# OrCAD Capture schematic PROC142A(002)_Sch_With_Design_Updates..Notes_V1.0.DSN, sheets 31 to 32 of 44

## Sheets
31 31. FT4232 UART TO USB BRIDGE: size C; title: FT4232 UART TO USB BRIDGE
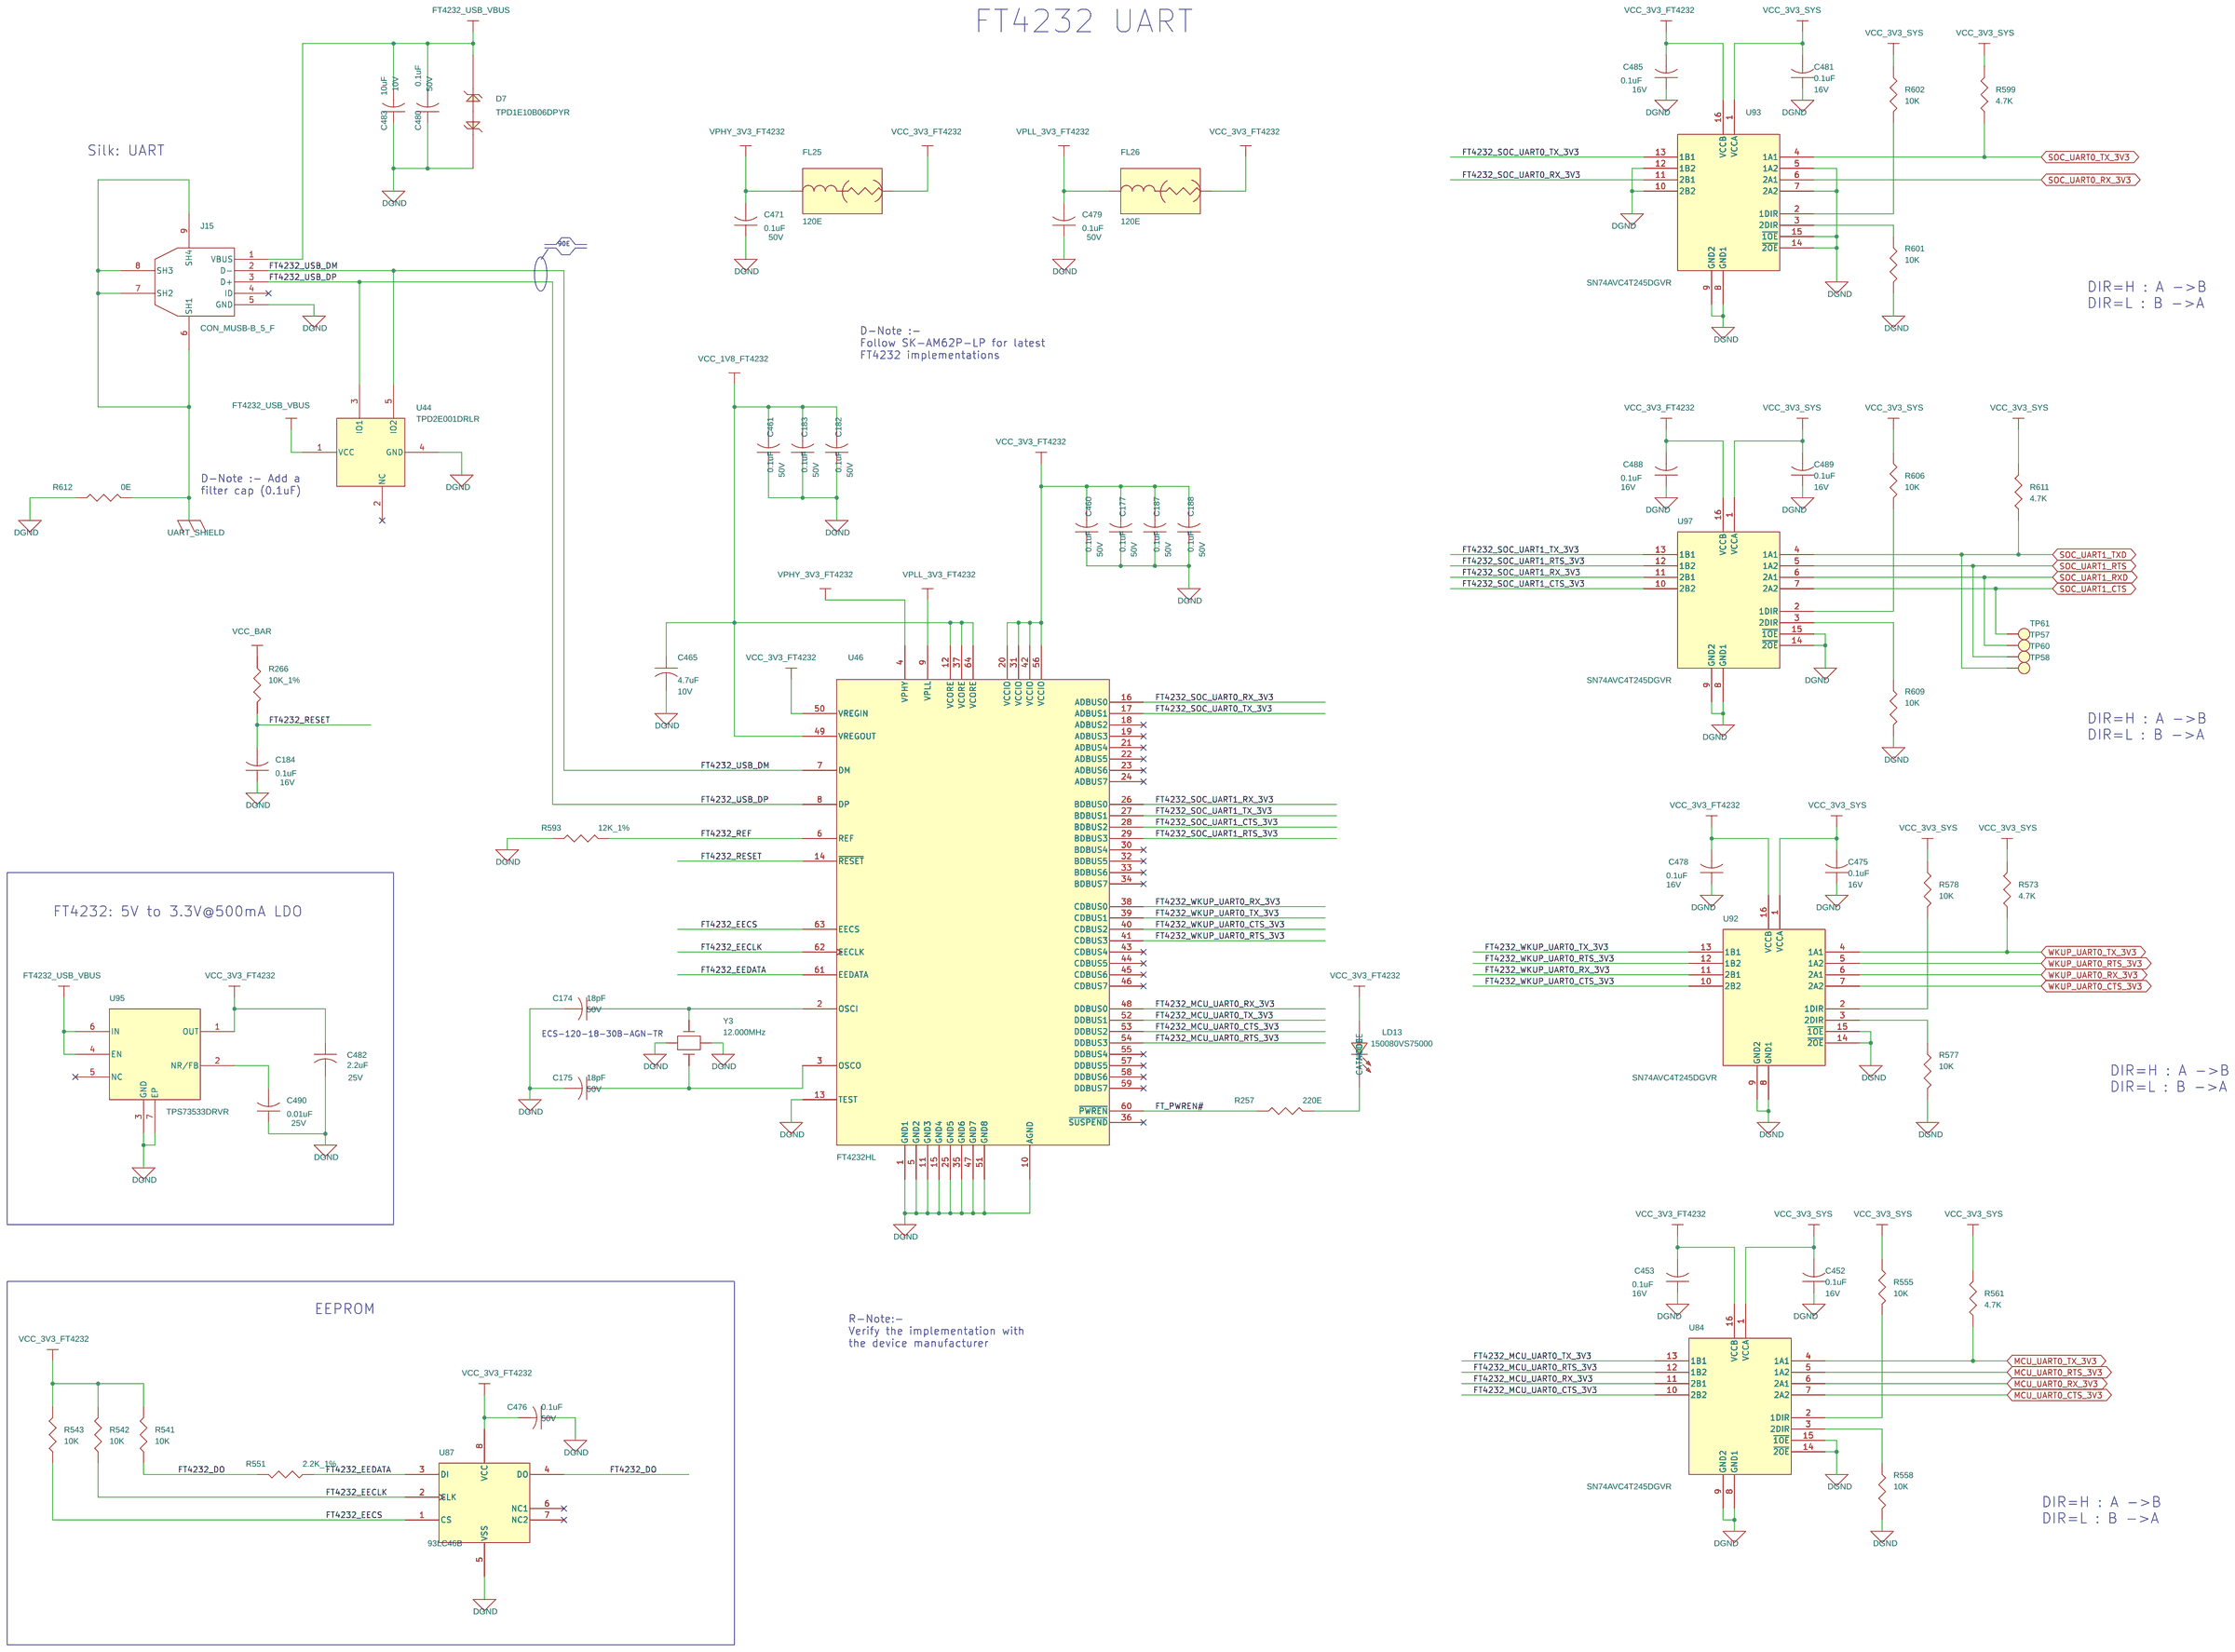
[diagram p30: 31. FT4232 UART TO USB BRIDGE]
32 32. PRU HEADER: size C; title: PRU HEADER
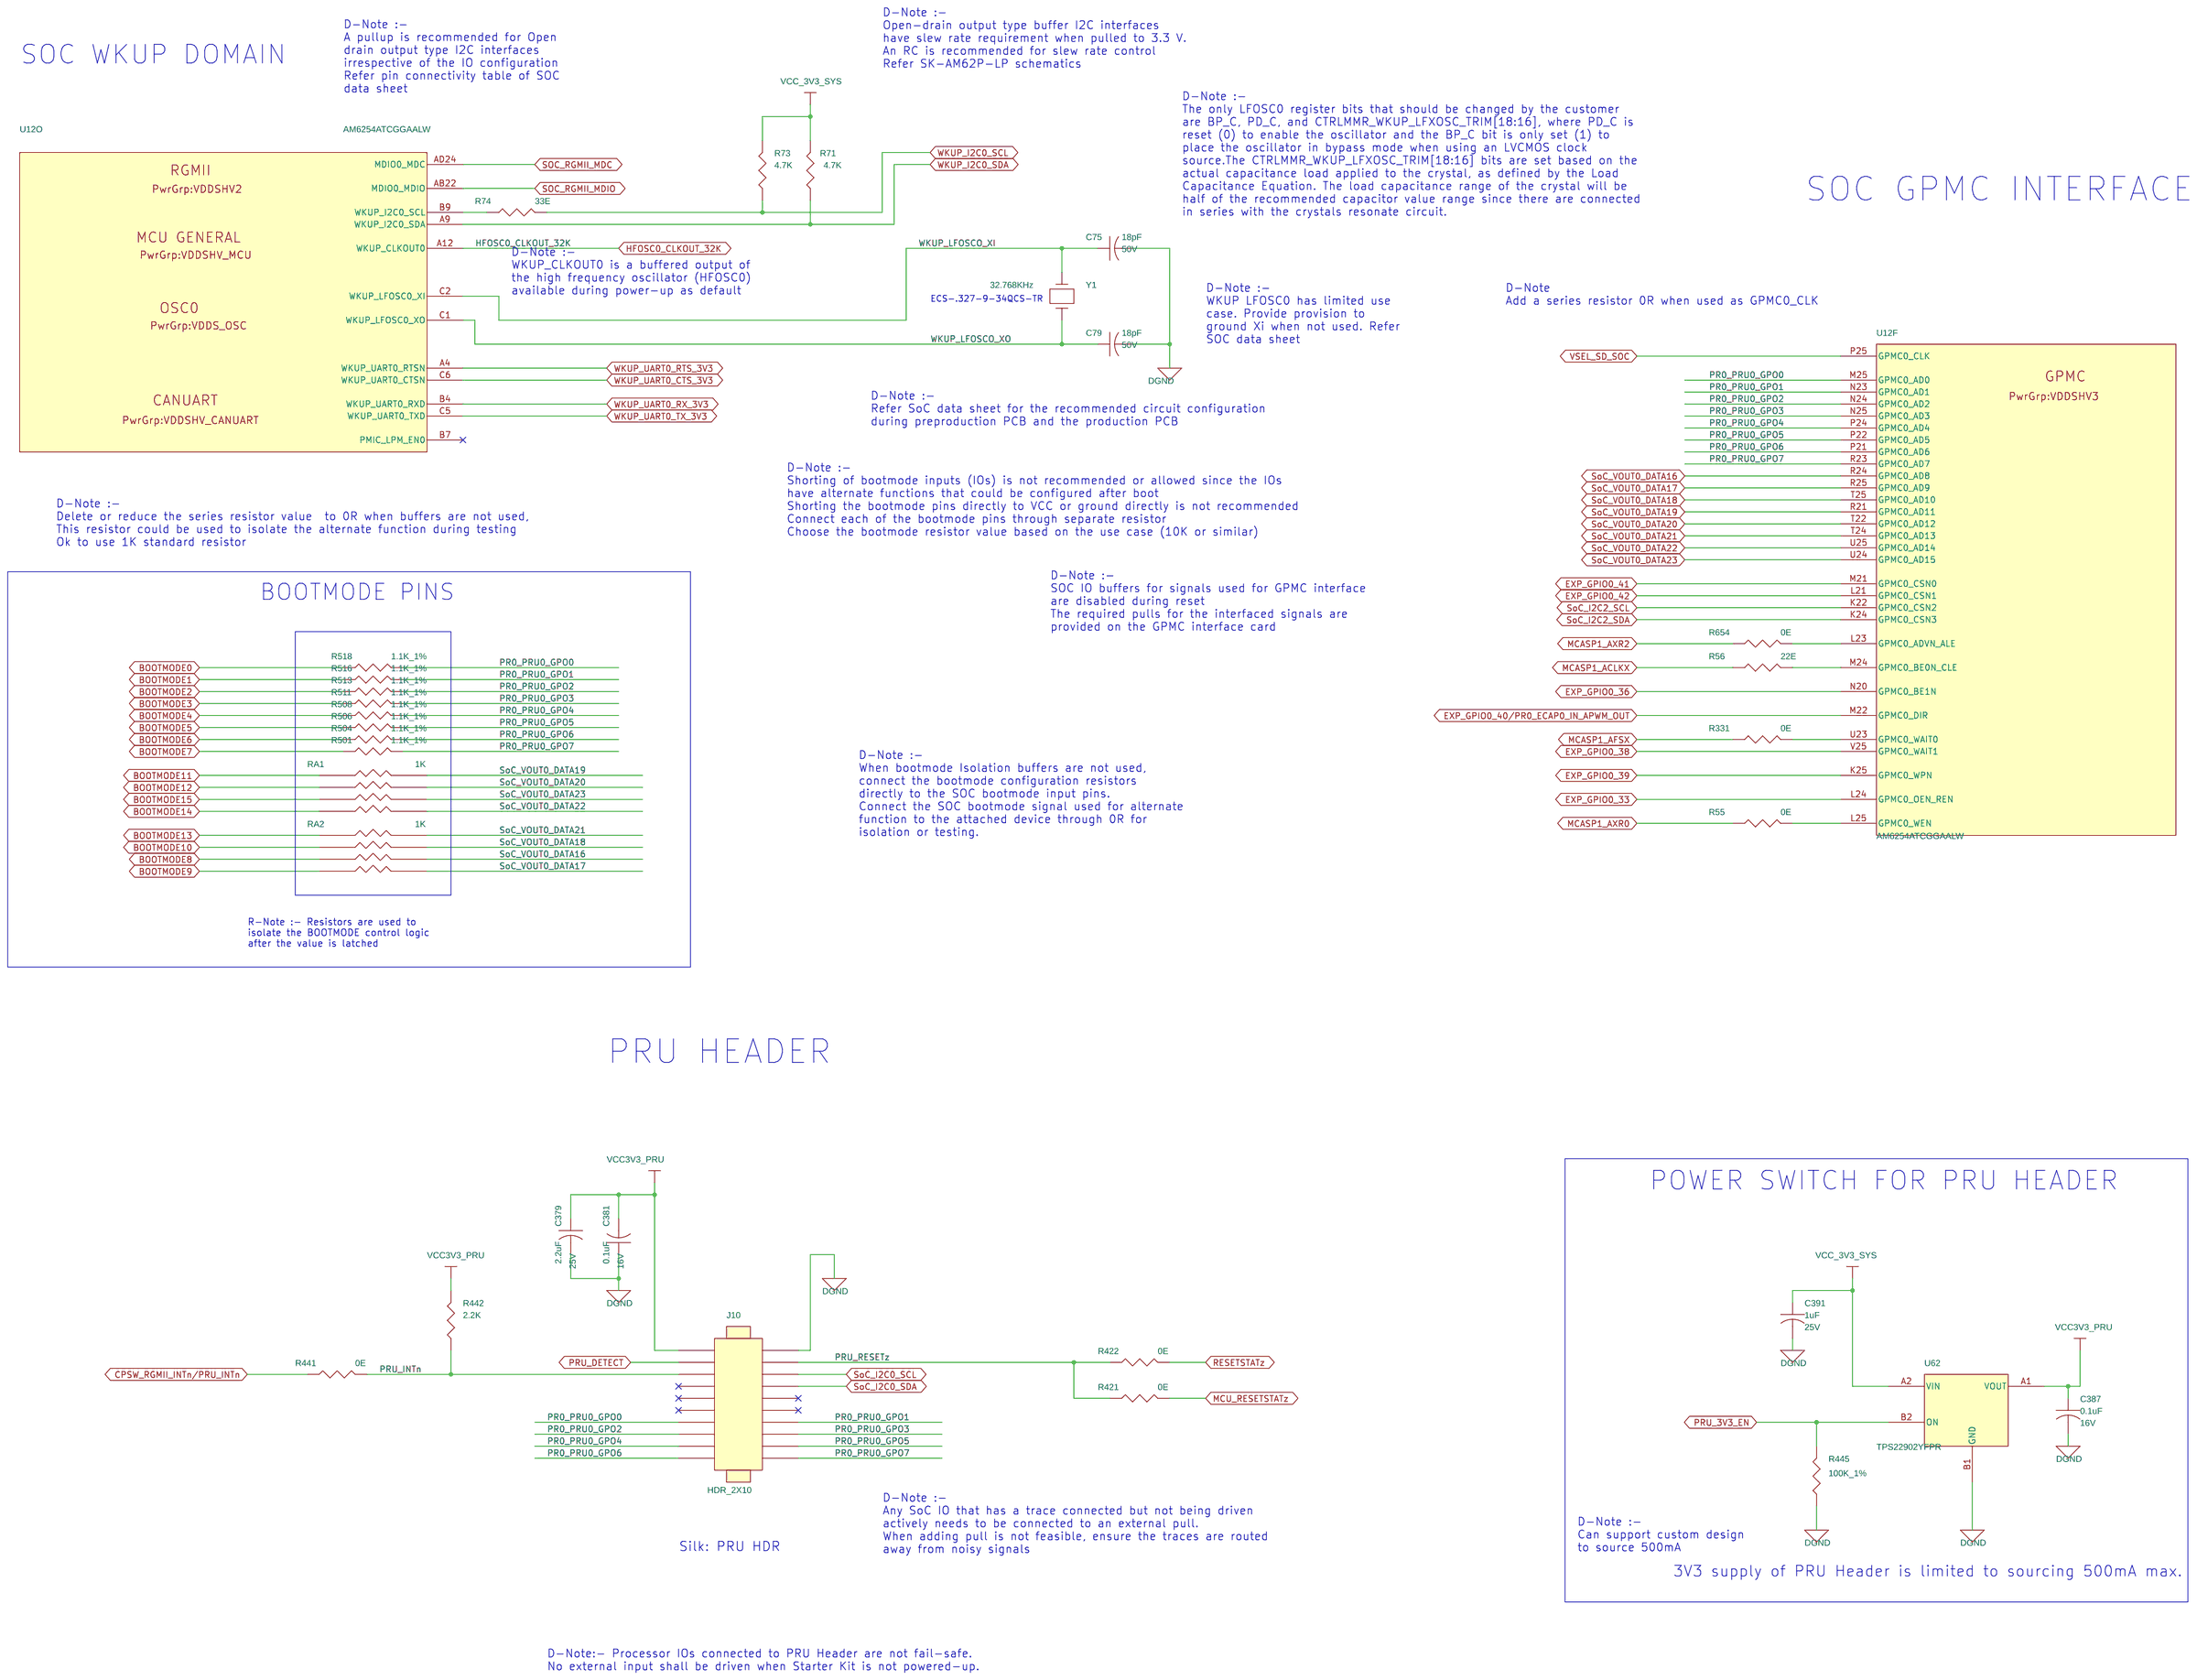
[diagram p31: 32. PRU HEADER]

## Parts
sheet 31. FT4232 UART TO USB BRIDGE
C174  18pF  [CAP0402_0-75]
C175  18pF  [CAP0402_0-75]
C177  0.1uF  [CAP0402_0-75]
C182  0.1uF  [CAP0402_0-75]
C183  0.1uF  [CAP0402_0-75]
C184  0.1uF  [CAP0201_0-5]
C187  0.1uF  [CAP0402_0-75]
C188  0.1uF  [CAP0402_0-75]
C452  0.1uF  [CAP0201_0-5]
C453  0.1uF  [CAP0201_0-5]
C460  0.1uF  [CAP0402_0-75]
C461  0.1uF  [CAP0402_0-75]
C465  4.7uF  [CAP0402_0-75]
C471  0.1uF  [CAP0402_0-75]
C475  0.1uF  [CAP0201_0-5]
C476  0.1uF  [CAP0402_0-75]
C478  0.1uF  [CAP0201_0-5]
C479  0.1uF  [CAP0402_0-75]
C480  0.1uF  [CAP0402_0-75]
C481  0.1uF  [CAP0201_0-5]
C482  2.2uF  [CAP0402_0-75]
C483  10uF  [CAP0402_0-75]
C485  0.1uF  [CAP0201_0-5]
C488  0.1uF  [CAP0201_0-5]
C489  0.1uF  [CAP0201_0-5]
C490  0.01uF  [CAP0201_0-5]
D7  TPD1E10B06DPYR  [DIO_DFN0402_0-5]
FL25  120E  [EMIFIL_BLM15A_0402_0-6]
FL26  120E  [EMIFIL_BLM15A_0402_0-6]
J15  CON_MUSB-B_5_F  [CON_MUSBB5_629105150521_S_R_S_2-7]
LD13  150080VS75000  [LED_150080VS75000_80X50_SMD_0-8]
R257  220E  [RES0402_0-5]
R266  10K_1%  [RES0201_0-5]
R541  10K  [RES0201_0-5]
R542  10K  [RES0201_0-5]
R543  10K  [RES0201_0-5]
R551  2.2K_1%  [RES0201_0-5]
R555  10K  [RES0201_0-5]
R558  10K  [RES0201_0-5]
R561  4.7K  [RES0201_0-5]
R573  4.7K  [RES0201_0-5]
R577  10K  [RES0201_0-5]
R578  10K  [RES0201_0-5]
R593  12K_1%  [RES0402_0-5]
R599  4.7K  [RES0201_0-5]
R601  10K  [RES0201_0-5]
R602  10K  [RES0201_0-5]
R606  10K  [RES0201_0-5]
R609  10K  [RES0201_0-5]
R611  4.7K  [RES0201_0-5]
R612  0E  [RES0805_0-75]
TP57  THRU HOLE  [TP_36X22]
TP58  THRU HOLE  [TP_36X22]
TP60  TP20_SMD  [TP20_SMD]
TP61  TP20_SMD  [TP20_SMD]
U44  TPD2E001DRLR  [SOT553-5_0-6]
U46  FT4232HL  [LQFP64_19-68_390X390_1-6]
U84  SN74AVC4T245DGVR  [TVSOP16_15-74_150X180]
U87  93LC46B  [MSOP8_25-59_125X125_1-1]
U92  SN74AVC4T245DGVR  [TVSOP16_15-74_150X180]
U93  SN74AVC4T245DGVR  [TVSOP16_15-74_150X180]
U95  TPS73533DRVR  [SON6_25-59_85X85]
U97  SN74AVC4T245DGVR  [TVSOP16_15-74_150X180]
Y3  12.000MHz  [XTAL4_ECX-53BQ_200X130_SMD_0-9]
sheet 32. PRU HEADER
C75  18pF  [CAP0402_0-75]
C79  18pF  [CAP0402_0-75]
C379  2.2uF  [CAP0402_0-75]
C381  0.1uF  [CAP0201_0-5]
C387  0.1uF  [CAP0201_0-5]
C391  1uF  [CAP0402_0-75]
J10  HDR_2X10  [HDR_2X10_PREC010DAAN_S_T_8-4]
R55  0E  [RES0201_0-5]
R56  22E  [RES0201_0-5]
R71  4.7K  [RES0201_0-5]
R73  4.7K  [RES0201_0-5]
R74  33E  [RES0201_0-5]
R331  0E  [RES0201_0-5]
R421  0E  [RES0402_0-5]
R422  0E  [RES0201_0-5]
R441  0E  [RES0201_0-5]
R442  2.2K  [RES0201_0-5]
R445  100K_1%  [RES0402_0-5]
R501  1.1K_1%  [RES0201_0-5]
R504  1.1K_1%  [RES0201_0-5]
R506  1.1K_1%  [RES0201_0-5]
R508  1.1K_1%  [RES0201_0-5]
R511  1.1K_1%  [RES0201_0-5]
R513  1.1K_1%  [RES0201_0-5]
R516  1.1K_1%  [RES0201_0-5]
R518  1.1K_1%  [RES0201_0-5]
R654  0E  [RES0201_0-5]
RA1  1K  [RESA_EXB_0201-4_0-5]
RA2  1K  [RESA_EXB_0201-4_0-5]
U62  TPS22902YFPR  [DSBGA4_15-74_30X30_0-5]
Y1  32.768KHz  [XTAL_ECS-32_130X60_SMD_0-9]
sheet 42. OSCILLATOR
U12  AM6254ATCGGAALW  [BGA425_19-68_510X510_0-7]  (sections A,B,C,D,E,F,G,H,I,J,K,L,M,N,O,P,Q,R)

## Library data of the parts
C75 C79 C174 C175 = CAP: CAP CERAMIC 18pF 50V 5% HI-Q C0G(NP0) 0402; Chkd/date: VASANTHA/030315; Crtd /date: NAVEED/271014; Custom_Duty: 15%; Customs_HS_Code: 85322990; Distributor_name: DIGIKEY; Distributor_part_number: 490-3119-1-ND; Footprint Path: Y:\MIS_DATABASE\Library\ALTIUM_TOOL\PCB_FOOTPRINTS\Altium_Footprint_Lib.PcbLib; Height: 0.55MM; Library Path: Y:\MIS_DATABASE\Library\ALTIUM_TOOL\SCHEMATICS_PARTS\MS_DISCRETE_Library.schlib; Mfr_name: MURATA; Mfr_part_number: GJM1555C1H180JB01D; Mistral Part No: 120014100019-R; Package: 0402; Part_type: CAPACITORS\CERAMIC; Project: DC_MIST_RDC; RoHS: RoHS; Temperature: -55°C+125°C; Tolerance: 5%; Voltage: 50V; Wattage: NA; Weight: 6mg; Datasheet: Y:\MIS_DATABASE\DATASHEETS\CAPACITORS\MURATA-GXX-SER_NOV17.PDF
C177 C182 C183 C187 C188 C460 C461 C471 C476 C479 C480 = CAP: CAP CERAMIC 0.1uF 50V 10% X7R 0402; Alt_Mfr_name: YAGEO AMERICA; Alt_Mfr_part_number: CC0402KRX5R8BB104; Chkd/date: MANIRAJA/261020; Crtd /date: ALVY/211020; Custom_Duty: 15%; Customs_HS_Code: 85322990; Distributor_name: DIGIKEY; Distributor_part_number: 490-10700-1-ND; Footprint Path: Y:\MIS_DATABASE\Library\ALTIUM_TOOL\PCB_FOOTPRINTS\Altium_Footprint_Lib.PcbLib; Height: 0.55MM; Library Path: Y:\MIS_DATABASE\Library\ALTIUM_TOOL\SCHEMATICS_PARTS\MS_DISCRETE_Library.schlib; Mfr_name: MURATA; Mfr_part_number: GRM155R71H104KE14D; Mistral Part No: 120011100014-R; Package: 0402; Part_type: CAPACITORS\CERAMIC; Project: J7_CP; RoHS: RoHS; Temperature: -55°C+125°C; Tolerance: 10%; Voltage: 50V; Wattage: NA; Weight: 3.1mg; Datasheet: Y:\MIS_DATABASE\DATASHEETS\CAPACITORS\GRM155R71H104KE14.PDF
C184 C381 C452 C453 C475 C478 C481 C485 C488 C489 = CAP: CAP CERAMIC 0.1uF 16V 10% X5R 0201; Alt_Mfr_name: YAGEO AMERICA; Alt_Mfr_part_number: CC0402KRX5R8BB104; Chkd/date: MANIRAJA/230118; Crtd /date: MANIRAJA/230118; Custom_Duty: 15%; Customs_HS_Code: 85322990; Distributor_name: DIGIKEY; Distributor_part_number: 490-14305-1-ND; Footprint Path: Y:\MIS_DATABASE\Library\ALTIUM_TOOL\PCB_FOOTPRINTS\Altium_Footprint_Lib.PcbLib; Height: 0.33MM; Library Path: Y:\MIS_DATABASE\Library\ALTIUM_TOOL\SCHEMATICS_PARTS\MS_DISCRETE_Library.schlib; Mfr_name: MURATA; Mfr_part_number: GRM033R61C104KE14D; Mistral Part No: 120009030072-R; Package: 0201; Part_type: CAPACITORS\CERAMIC; Project: TI_MAXIE_CPB; RoHS: RoHS; Temperature: -55°C+85°C; Tolerance: 10%; Voltage: 16V; Wattage: NA; Weight: 0.33mg; Datasheet: Y:\MIS_DATABASE\DATASHEETS\CAPACITORS\GRM033R61C104KE14.PDF
C465 = CAP: CAP CERAMIC 4.7uF 10V 20% X5R 0402; Chkd/date: MANIRAJA/110718; Crtd /date: ALVY/110718; Custom_Duty: 15%; Customs_HS_Code: 85322990; Distributor_name: DIGIKEY; Distributor_part_number: 490-14306-1-ND; Footprint Path: Y:\MIS_DATABASE\Library\ALTIUM_TOOL\PCB_FOOTPRINTS\Altium_Footprint_Lib.PcbLib; Height: 0.65MM; Library Path: Y:\MIS_DATABASE\Library\ALTIUM_TOOL\SCHEMATICS_PARTS\MS_DISCRETE_Library.schlib; Mfr_name: MURATA; Mfr_part_number: GRM155R61A475MEAAD; Mistral Part No: 120012060002-R; Package: 0402; Part_type: CAPACITORS\CERAMIC; Project: TI_J7SVB_PCIE_ADD-ON-CARD; RoHS: RoHS; Temperature: -55°C+85°C; Tolerance: 20%; Voltage: 10V; Wattage: NA; Weight: 14mg; Datasheet: Y:\MIS_DATABASE\DATASHEETS\CAPACITORS\GRM155R61A475MEAAD.PDF
C379 C482 = CAP: CAP CERAMIC 2.2uF 25V 10% X5R 0402; Chkd/date: ALVY/010721; Crtd /date: MANIRAJA/010721; Custom_Duty: 15%; Customs_HS_Code: 85322990; Distributor_name: DIGIKEY; Distributor_part_number: 490-12703-1-ND; Footprint Path: Y:\MIS_DATABASE\Library\ALTIUM_TOOL\PCB_FOOTPRINTS\Altium_Footprint_Lib.PcbLib; Height: 0.70MM; Library Path: Y:\MIS_DATABASE\Library\ALTIUM_TOOL\SCHEMATICS_PARTS\MS_DISCRETE_Library.schlib; Mfr_name: MURATA; Mfr_part_number: GRM155R61E225KE11D; Mistral Part No: 120015120001-R; Package: 0402; Part_type: CAPACITORS\CERAMIC; Project: TI_AM263X_CC; RoHS: RoHS; Temperature: -55°C+85°C; Tolerance: 10%; Voltage: 25V; Wattage: NA; Weight: 1.5mg; Datasheet: Y:\MIS_DATABASE\DATASHEETS\CAPACITORS\GRM155R61E225KE11.PDF
C483 = CAP: CAP CERAMIC 10uF 10V 20% X5R 0402; Chkd/date: MANIRAJA/300520; Crtd /date: ALVY/260520; Custom_Duty: 15%; Customs_HS_Code: 85322990; Distributor_name: DIGIKEY; Distributor_part_number: 490-GRM155R61A106ME11DTR-ND; Footprint Path: Y:\MIS_DATABASE\Library\ALTIUM_TOOL\PCB_FOOTPRINTS\Altium_Footprint_Lib.PcbLib; Height: 0.55MM; Library Path: Y:\MIS_DATABASE\Library\ALTIUM_TOOL\SCHEMATICS_PARTS\MS_DISCRETE_Library.schlib; Mfr_name: MURATA; Mfr_part_number: GRM155R61A106ME11D; Mistral Part No: 120013110019-R; Package: 0402; Part_type: CAPACITORS\CERAMIC; Project: QCS610_NANOSOM; RoHS: RoHS; Temperature: -55°C+85°C; Tolerance: 20%; Voltage: 10V; Wattage: NA; Weight: 3.1mg; Datasheet: Y:\MIS_DATABASE\DATASHEETS\CAPACITORS\MURATA-GXX-SER_NOV17.PDF
C490 = CAP: CAP CERAMIC 0.01uF 25V 10% X5R 0201; Chkd/date: MANIRAJA/230118; Crtd /date: MANIRAJA/230118; Custom_Duty: 15%; Customs_HS_Code: 85322990; Distributor_name: DIGIKEY; Distributor_part_number: GRM033R61E103KA12J-ND; Footprint Path: Y:\MIS_DATABASE\Library\ALTIUM_TOOL\PCB_FOOTPRINTS\Altium_Footprint_Lib.PcbLib; Height: 0.33MM; Library Path: Y:\MIS_DATABASE\Library\ALTIUM_TOOL\SCHEMATICS_PARTS\MS_DISCRETE_Library.schlib; Mfr_name: MURATA; Mfr_part_number: GRM033R61E103KA12J; Mistral Part No: 120018010007-R; Package: 0201; Part_type: CAPACITORS\CERAMIC; Project: TI_MAXIE_CPB; RoHS: RoHS; Temperature: -55°C+85°C; Tolerance: 10%; Voltage: 25V; Wattage: NA; Weight: 0.33mg; Datasheet: Y:\MIS_DATABASE\DATASHEETS\CAPACITORS\GRM033R61E103KA12.PDF
D7 = DIODE_SOD323: DIODE 1CH ESD PROTECTION X1SON2; Chkd/date: MANIRAJA/040420; Crtd /date: VASANTHA/181114; Custom_Duty: 15%; Customs_HS_Code: 85423100; Distributor_name: DIGIKEY; Distributor_part_number: 296-30406-1-ND; Footprint Path: Y:\MIS_DATABASE\Library\ALTIUM_TOOL\PCB_FOOTPRINTS\Altium_Footprint_Lib.PcbLib; Height: 0.45MM; Library Path: Y:\MIS_DATABASE\Library\ALTIUM_TOOL\SCHEMATICS_PARTS\MS_DISCRETE_Library.schlib; Mfr_name: TEXAS INSTRUMENTS; Mistral Part No: 130014110022-R; Package: X1SON2; Part_type: DIODE; Project: GALILEO_EVM; RoHS: RoHS; Temperature: -40°C+125°C; Tolerance: NA; Voltage: NA; Wattage: NA; Weight: 1mg; Datasheet: Y:\MIS_DATABASE\DATASHEETS\ICS\INTERFACE\TPD1E10B06-SER.PDF
FL25 FL26 = EMIFILTER_IND: IND FERRITE BEAD CHIP 120E 2A 0402; Chkd/date: NAVEED/241114; Crtd /date: USMAN/170613; Custom_Duty: 24%; Customs_HS_Code: 85369090; Distributor_name: DIGIKEY; Distributor_part_number: 490-9656-1-ND; Footprint Path: Y:\MIS_DATABASE\Library\ALTIUM_TOOL\PCB_FOOTPRINTS\Altium_Footprint_Lib.PcbLib; Height: 0.55MM; Library Path: Y:\MIS_DATABASE\Library\ALTIUM_TOOL\SCHEMATICS_PARTS\MS_FILTER_Library.schlib; Mfr_name: MURATA; Mfr_part_number: BLM15PX121SN1D; Mistral Part No: 130013060022-R; Package: 0402; Part_type: INDUCTOR; Project: GEN_3-8; RoHS: RoHS; Temperature: -55°C+125°C; Tolerance: 25%; Voltage: NA; Wattage: NA; Weight: 1mg; Datasheet: Y:\MIS_DATABASE\DATASHEETS\DISCRETES\INDUCTORS\BLM15-SN1-SER.PDF
J15 = CON_USB_MINI-B: CON MICRO USB TYPE B 5POS FEMALE RT SMD; Chkd/date: MANIRAJA/150519; Crtd /date: ALVY/150519; Custom_Duty: 24%; Customs_HS_Code: 85369090; Distributor_name: DIGIKEY; Distributor_part_number: 732-5960-1-ND; Footprint Path: Y:\MIS_DATABASE\Library\ALTIUM_TOOL\PCB_FOOTPRINTS\Altium_Footprint_Lib.PcbLib; Height: 2.66MM; Library Path: Y:\MIS_DATABASE\Library\ALTIUM_TOOL\SCHEMATICS_PARTS\MS_CONNECTOR_Library.schlib; Mfr_name: WURTH ELECTRONICS; Mfr_part_number: 629105150521; Mistral Part No: 150019050015-R; Package: SMD; Part_type: CONNECTOR\USB; Project: NEXTNAV_ALT-STATION_ATE_BRD; RoHS: RoHS; Temperature: -40°C+85°C; Tolerance: NA; Voltage: NA; Wattage: NA; Weight: 360mg; Datasheet: Y:\MIS_DATABASE\DATASHEETS\CONNECTORS\629105150521.PDF
LD13 = DIODE_LED: DIODE LED BRIGHT GREEN SMD; Chkd/date: MANIRAJA/180820; Crtd /date: ALVY/180820; Custom_Duty: 24%; Customs_HS_Code: 85439000; Distributor_name: DIGIKEY; Distributor_part_number: 732-4986-1-ND; Footprint Path: Y:\MIS_DATABASE\Library\ALTIUM_TOOL\PCB_FOOTPRINTS\Altium_Footprint_Lib.PcbLib; Height: 0.80MM; Library Path: Y:\MIS_DATABASE\Library\ALTIUM_TOOL\SCHEMATICS_PARTS\MS_OPTO_Library.schlib; Mfr_name: WURTH ELECTRONICS; Mistral Part No: 130020080012-R; Package: SMD; Part_type: OPTO\LED; Project: AM64x_EVM_BRD; RoHS: RoHS; Temperature: -40°C+85°C; Tolerance: NA; Voltage: NA; Wattage: NA; Weight: 10mg; Datasheet: Y:\MIS_DATABASE\DATASHEETS\DISCRETES\LEDS\150080VS75000.PDF
R257 = RESISTOR: RES 220E 1/10W 5% 0402; Chkd/date: VASANTHA/291216; Crtd /date: GEETHA/260406; Custom_Duty: 15%; Customs_HS_Code: 85332119; Distributor_name: DIGIKEY; Distributor_part_number: P220JCT-ND; Footprint Path: Y:\MIS_DATABASE\Library\ALTIUM_TOOL\PCB_FOOTPRINTS\Altium_Footprint_Lib.PcbLib; Height: 0.40MM; Library Path: Y:\MIS_DATABASE\Library\ALTIUM_TOOL\SCHEMATICS_PARTS\MS_DISCRETE_Library.schlib; Mfr_name: PANASONIC-ECG; Mfr_part_number: ERJ-2GEJ221X; Mistral Part No: 110009030506-R; Package: 0402; Part_type: RESISTORS\FIXED; Project: RED EYE; RoHS: RoHS; Temperature: -55°C+155°C; Tolerance: 5%; Voltage: NA; Wattage: 1/10W; Weight: 0.8mg; Datasheet: Y:\MIS_DATABASE\DATASHEETS\RESISTORS\PAN-ERJSER_NOV17.PDF
R266 = RESISTOR: RES 10K 1/20W 1% 0201; Chkd/date: VASANTHA/270117; Crtd /date: MANIRAJA/270117; Custom_Duty: 15%; Customs_HS_Code: 85332119; Distributor_name: DIGIKEY; Distributor_part_number: 311-10.0KMCT-ND; Footprint Path: Y:\MIS_DATABASE\Library\ALTIUM_TOOL\PCB_FOOTPRINTS\Altium_Footprint_Lib.PcbLib; Height: 0.26MM; Library Path: Y:\MIS_DATABASE\Library\ALTIUM_TOOL\SCHEMATICS_PARTS\MS_DISCRETE_Library.schlib; Mfr_name: YAGEO AMERICA; Mfr_part_number: RC0201FR-0710KL; Mistral Part No: 110011040018-R; Package: 0201; Part_type: RESISTORS\FIXED; Project: GOLDEN-I LITE; RoHS: RoHS; Temperature: -55°C+125°C; Tolerance: 1%; Voltage: NA; Wattage: 1/20W; Weight: 0.17mg; Datasheet: Y:\MIS_DATABASE\DATASHEETS\RESISTORS\RCXXXXL-SER_MAR18.PDF
R541-R543 R555 R558 R577 R578 R601 R602 R606 R609 = RESISTOR: RES 10K 1/20W 5% 0201; Chkd/date: MANIRAJA/050517; Crtd /date: MANIRAJA/050517; Custom_Duty: 15%; Customs_HS_Code: 85332119; Distributor_name: DIGIKEY; Distributor_part_number: 311-10KNCT-ND; Footprint Path: Y:\MIS_DATABASE\Library\ALTIUM_TOOL\PCB_FOOTPRINTS\Altium_Footprint_Lib.PcbLib; Height: 0.26MM; Library Path: Y:\MIS_DATABASE\Library\ALTIUM_TOOL\SCHEMATICS_PARTS\MS_DISCRETE_Library.schlib; Mfr_name: YAGEO AMERICA; Mfr_part_number: RC0201JR-0710KL; Mistral Part No: 110010070051-R; Package: 0201; Part_type: RESISTORS\FIXED; Project: GOLDEN-I LITE; RoHS: RoHS; Temperature: -55°C+125°C; Tolerance: 5%; Voltage: NA; Wattage: 1/20W; Weight: 0.17mg; Datasheet: Y:\MIS_DATABASE\DATASHEETS\RESISTORS\RCXXXXL-SER_MAR18.PDF
R551 = RESISTOR: RES 2.2K 1/20W 1% 0201; Chkd/date: VASANTHA/270117; Crtd /date: MANIRAJA/270117; Custom_Duty: 15%; Customs_HS_Code: 85332119; Distributor_name: DIGIKEY; Distributor_part_number: YAG2572CT-ND; Footprint Path: Y:\MIS_DATABASE\Library\ALTIUM_TOOL\PCB_FOOTPRINTS\Altium_Footprint_Lib.PcbLib; Height: 0.26MM; Library Path: Y:\MIS_DATABASE\Library\ALTIUM_TOOL\SCHEMATICS_PARTS\MS_DISCRETE_Library.schlib; Manufacturer: YAGEO AMERICA; Mfr_name: PANASONIC-ECG; Mfr_part_number: RC0201FR-072K2L; Mistral Part No: 110017010016-R; Package: 0201; Part_type: RESISTORS\FIXED; Project: GOLDEN-I LITE; RoHS: RoHS; Temperature: -55°C+125°C; Tolerance: 1%; Voltage: NA; Wattage: 1/20W; Weight: 0.17mg; Datasheet: Y:\MIS_DATABASE\DATASHEETS\RESISTORS\RCXXXXL-SER_MAR18.PDF
R71 R73 R561 R573 R599 R611 = RESISTOR: RES 4.7K 1/20W 5% 0201; Chkd/date: MANIRAJA/200921; Crtd /date: ALVY/200921; Custom_Duty: 15%; Customs_HS_Code: 85332119; Distributor_name: DIGIKEY; Distributor_part_number: 311-4.7KNCT-ND; Footprint Path: Y:\MIS_DATABASE\Library\ALTIUM_TOOL\PCB_FOOTPRINTS\Altium_Footprint_Lib.PcbLib; Height: 0.26MM; Library Path: Y:\MIS_DATABASE\Library\ALTIUM_TOOL\SCHEMATICS_PARTS\MS_DISCRETE_Library.schlib; Mfr_name: YAGEO AMERICA; Mfr_part_number: RC0201JR-074K7L; Mistral Part No: 110021090007-R; Package: 0201; Part_type: RESISTORS\FIXED; Project: TI_AM62x SKEVM_BRD; RoHS: RoHS; Temperature: -55°C+125°C; Tolerance: 5%; Voltage: NA; Wattage: 1/20W; Weight: 0.17mg; Datasheet: Y:\MIS_DATABASE\DATASHEETS\RESISTORS\RCXXXXL-SER_MAR18.PDF
R593 = RESISTOR: RES 12K 1/10W 1% 0402; Chkd/date: VASANTHA/041215; Crtd /date: VASANTHA/041215; Custom_Duty: 15%; Customs_HS_Code: 85332119; Distributor_name: DIGIKEY; Distributor_part_number: P12.0KLCT-ND; Footprint Path: Y:\MIS_DATABASE\Library\ALTIUM_TOOL\PCB_FOOTPRINTS\Altium_Footprint_Lib.PcbLib; Height: 0.40MM; Library Path: Y:\MIS_DATABASE\Library\ALTIUM_TOOL\SCHEMATICS_PARTS\MS_DISCRETE_Library.schlib; Mfr_name: PANASONIC-ECG; Mfr_part_number: ERJ-2RKF1202X; Mistral Part No: 110019040053-R; Package: 0402; Part_type: RESISTORS\FIXED; Project: TI_C5545; RoHS: RoHS; Temperature: -55°C+155°C; Tolerance: 1%; Voltage: NA; Wattage: 1/10W; Weight: 0.8mg; Datasheet: Y:\MIS_DATABASE\DATASHEETS\RESISTORS\PAN-ERJSER_NOV17.PDF
R612 = RESISTOR: RES 0E 1/8W 5% 0805; Chkd/date: VASANTHA/130416; Crtd /date: JEBRAN/020316; Custom_Duty: 15%; Customs_HS_Code: 85332119; Distributor_name: DIGIKEY; Distributor_part_number: 311-0.0ARCT-ND; Footprint Path: Y:\MIS_DATABASE\Library\ALTIUM_TOOL\PCB_FOOTPRINTS\Altium_Footprint_Lib.PcbLib; Height: 0.60MM; Library Path: Y:\MIS_DATABASE\Library\ALTIUM_TOOL\SCHEMATICS_PARTS\MS_DISCRETE_Library.schlib; Mfr_name: YAGEO AMERICA; Mfr_part_number: RC0805JR-070RL; Mistral Part No: 110009030074-R; Package: 0805; Part_type: RESISTORS\FIXED; Project: ZK_BIOMETRIC; RoHS: RoHS; Temperature: -55°C+155°C; Tolerance: 5%; Voltage: NA; Wattage: 1/8W; Weight: 5.5mg; Datasheet: Y:\MIS_DATABASE\DATASHEETS\RESISTORS\RCXXXXL-SER_MAR18.PDF
TP57 TP58 = TESTPOINT: TESTPOINT 0.56MM DRILL PTH; Chkd/date: BAVISH/040311; Crtd /date: MAZHAR/110405; Distributor_name: NA; Distributor_part_number: NA; Height: NA; Mfr_name: LOCAL; Mistral Part No: 130010010008; Package: THRU-HOLE; Project: KOPIN_MODULS; Temperature: NA; Tolerance: NA; Voltage: NA; Wattage: NA; Weight: NA; Datasheet: NA
TP60 TP61 = TESTPOINT: TESTPOINT CIR 20 SMD; Chkd/date: SHREESHAIL/171006; Crtd /date: MAZHAR/171006; Custom_Duty: NA; Customs_HS_Code: NA; Distributor_name: NA; Distributor_part_number: NA; Footprint Path: Y:\MIS_DATABASE\Library\ALTIUM_TOOL\PCB_FOOTPRINTS\Altium_Footprint_Lib.PcbLib; Height: NA; Library Path: Y:\MIS_DATABASE\Library\ALTIUM_TOOL\SCHEMATICS_PARTS\MS_DISCRETE_Library.schlib; MECHANICAL 3D STEP FILE: NA; Mfr_name: LOCAL; Mistral Part No: NA; Package: SMD; Project: BT MODULE_CSRBC04; RoHS: NA; Temperature: NA; Tolerance: NA; Voltage: NA; Wattage: NA; Weight: NA; Datasheet: NA
U44 = TPD2E001DRLR_SOT-5: IC ESD-PROTECTION DIODE ARRAYS SOT-5; Chkd/date: NAVEED/150714; Crtd /date: MUDDU/250510; Custom_Duty: 15%; Customs_HS_Code: 85423100; Distributor_name: DIGIKEY; Distributor_part_number: 296-21883-1-ND; Footprint Path: Y:\MIS_DATABASE\Library\ALTIUM_TOOL\PCB_FOOTPRINTS\Altium_Footprint_Lib.PcbLib; Height: 0.60MM; Library Path: Y:\MIS_DATABASE\Library\ALTIUM_TOOL\SCHEMATICS_PARTS\MS_FILTER_Library.schlib; Mfr_name: TEXAS INSTRUMENTS; Mistral Part No: 140110060007-R; Package: SOT-5; Part_type: ICS\ANALOG\ACTIVE FILTER; Project: CENTAURUS; RoHS: RoHS; Temperature: -40°C+85°C; Tolerance: NA; Voltage: NA; Wattage: NA; Weight: 2.8mg; Datasheet: Y:\MIS_DATABASE\DATASHEETS\ICS\MISC\TPD2E001DRLR.PDF
U46 = FT4232H_LQFP64: IC HIGH SPEED QUAD USB UART LQFP64; Chkd/date: MANIRAJA/110917; Crtd /date: VIJAYALAKSHMI/120813; Custom_Duty: 15%; Customs_HS_Code: 85423100; Distributor_name: DIGIKEY; Distributor_part_number: 768-1026-1-ND; Footprint Path: Y:\MIS_DATABASE\Library\ALTIUM_TOOL\PCB_FOOTPRINTS\Altium_Footprint_Lib.PcbLib; Height: 1.60MM; Library Path: Y:\MIS_DATABASE\Library\ALTIUM_TOOL\SCHEMATICS_PARTS\MS_COMBINATIONAL_Library.schlib; Mfr_name: FTDI; Mfr_part_number: FT4232HL-REEL; Mistral Part No: 141013080006-R; Package: LQFP64; Part_type: ICS\DIGITAL\PERIPHERAL; Project: DM37XX; RoHS: RoHS; Temperature: -40°C+85°C; Tolerance: NA; Voltage: NA; Wattage: NA; Weight: 342.7mg; Datasheet: Y:\MIS_DATABASE\DATASHEETS\ICS\DIGITAL\PERIPHERAL\FT4232HX.PDF
U84 U92 U93 U97 = SN74AVC4T245DGVR_TVSOP16: IC 4-BIT DUAL SUPPLY BUS TRANSCEIVER TVSOP16; Chkd/date: SUHAS/251010; Crtd /date: MAZHAR/201109; Custom_Duty: 15%; Customs_HS_Code: 85423100; Distributor_name: DIGIKEY; Distributor_part_number: 296-18054-1-ND; Height: 1.20MM; Mfr_name: TEXAS INSTRUMENTS; Mistral Part No: 141009110005-P; Package: TVSOP16; Part_type: ICS\DIGITAL\COMBINATIONAL; Project: GOLDEN-I; RoHS: Sb/ Br FREE; Temperature: -40°C+85°C; Datasheet: Y:\MIS_DATABASE\DATASHEETS\ICS\DIGITAL\BUSTRANSCEIVER\SN74AVC4T245.PDF
U87 = 93LC46B_MSOP8: IC 1K MICROWIRE COMPATIBLE SERIAL EEPROM MSOP8; Chkd/date: MANIRAJA/150218; Crtd /date: ALVY/150218; Custom_Duty: 15%; Customs_HS_Code: 85423100; Distributor_name: DIGIKEY; Distributor_part_number: 93LC46B-I/MS-ND; Footprint Path: Y:\MIS_DATABASE\Library\ALTIUM_TOOL\PCB_FOOTPRINTS\Altium_Footprint_Lib.PcbLib; Height: 1.10MM; Library Path: Y:\MIS_DATABASE\Library\ALTIUM_TOOL\SCHEMATICS_PARTS\MS_MISCMEMORY_Library.schlib; Mfr_name: MICROCHIP; Mfr_part_number: 93LC46B-I/MS; Mistral Part No: 141118020002-R; Package: MSOP8; Part_type: ICS\DIGITAL\MEMORY; Project: TI_MAXIE_CPB; RoHS: RoHS; Temperature: -40°C+85°C; Tolerance: NA; Voltage: NA; Wattage: NA; Weight: 140mg; Datasheet: Y:\MIS_DATABASE\DATASHEETS\ICS\MEMORY\93LC46B.PDF
U95 = TPS73501DRVR_SON6: IC 500mA LOW DROPOUT REGULATOR SON6; Chkd/date: VASANTHA/280915; Crtd /date: NAVEED/011014; Custom_Duty: 15%; Customs_HS_Code: 85423100; Distributor_name: DIGIKEY; Distributor_part_number: TPS73533DRVR-ND; Height: 0.80MM; Mfr_name: TEXAS INSTRUMENTS; Mistral Part No: 142014100001-R; Package: SON6; Part_type: ICS\POWER\VOLTAGE REGULATOR; Project: BLUETOOTH_WATCH; RoHS: RoHS; Temperature: -40°C+125°C; Tolerance: NA; Voltage: NA; Wattage: NA; Weight: NA; Datasheet: Y:\MIS_DATABASE\DATASHEETS\ICS\POWER\TPS735.PDF
Y3 = CRY4_13: CRY 12.000MHz 18pF SMD; Chkd/date: MANIRAJA/271021; Crtd /date: ALVY/271021; Custom_Duty: 24%; Customs_HS_Code: 85439000; Distributor_name: DIGIKEY; Distributor_part_number: XC2719CT-ND; Footprint Path: Y:\MIS_DATABASE\Library\ALTIUM_TOOL\PCB_FOOTPRINTS\Altium_Footprint_Lib.PcbLib; Height: 0.85MM; Library Path: Y:\MIS_DATABASE\Library\ALTIUM_TOOL\SCHEMATICS_PARTS\MS_DISCRETE_Library.schlib; Mfr_name: ECS INC; Mfr_part_number: ECS-120-18-30B-AGN-TR; Mistral Part No: 130021100037-R; Package: SMD; Part_type: CRYSTAL; Project: TI_AM62x SKEVM_BRD; RoHS: RoHS; Temperature: -40°C+85°C; Tolerance: NA; Voltage: NA; Wattage: NA; Weight: 159.425mg; Datasheet: Y:\MIS_DATABASE\DATASHEETS\MISC\CRY_OSC\ECS-53B.PDF
C387 = CAP: CAP CERAMIC 0.1uF 16V 10% X5R 0201; Chkd/date: PRADEEP/130623; Crtd /date: PRADEEP/130623; Custom_Duty: 15%; Customs_HS_Code: 85322990; Distributor_name: NA; Distributor_part_number: NA; Footprint Path: Y:\MIS_DATABASE\Library\ALTIUM_TOOL\PCB_FOOTPRINTS\Altium_Footprint_Lib.PcbLib; Height: 0.33MM; Library Path: Y:\MIS_DATABASE\Library\ALTIUM_TOOL\SCHEMATICS_PARTS\MS_DISCRETE_Library.schlib; Mfr_name: MURATA; Mfr_part_number: GRT033R61C104KE01; Mistral Part No: 120022060019-R; Package: 0201; Part_type: CAPACITORS\CERAMIC; Project: AM62P_SK; RoHS: RoHS; Temperature: -55°C+85°C; Tolerance: 10%; Voltage: 16V; Wattage: NA; Weight: 0.33mg; Datasheet: Y:\MIS_DATABASE\DATASHEETS\CAPACITORS\GRT033R61C104KE01XX.PDF
C391 = CAP: CAP CERAMIC 1uF 25V 10% X6S 0402; Chkd/date: MANIRAJA/140518; Crtd /date: ALVY/140518; Custom_Duty: 15%; Customs_HS_Code: 85322990; Distributor_name: DIGIKEY; Distributor_part_number: 490-10014-1-ND; Footprint Path: Y:\MIS_DATABASE\Library\ALTIUM_TOOL\PCB_FOOTPRINTS\Altium_Footprint_Lib.PcbLib; Height: 0.60MM; Library Path: Y:\MIS_DATABASE\Library\ALTIUM_TOOL\SCHEMATICS_PARTS\MS_DISCRETE_Library.schlib; Mfr_name: MURATA; Mfr_part_number: GRM155C81E105KE11D; Mistral Part No: 120018050004-R; Package: 0402; Part_type: CAPACITORS\CERAMIC; Project: TI_SVB_MAXWELL_DUT; RoHS: RoHS; Temperature: -55°C+105°C; Tolerance: 10%; Voltage: 25V; Wattage: NA; Weight: 6mg; Datasheet: Y:\MIS_DATABASE\DATASHEETS\CAPACITORS\GRM155C81E105KE11X.PDF
J10 = HEADER_10X2: CON HDR 2X10 2.54MM PITCH ST TH; Chkd/date: MANIRAJA/270721; Crtd /date: ALVY/260721; Custom_Duty: 24%; Customs_HS_Code: 85369090; Distributor_name: DIGIKEY; Distributor_part_number: S2012EC-10-ND; Footprint Path: Y:\MIS_DATABASE\Library\ALTIUM_TOOL\PCB_FOOTPRINTS\Altium_Footprint_Lib.PcbLib; Height: 8.34MM; Library Path: Y:\MIS_DATABASE\Library\ALTIUM_TOOL\SCHEMATICS_PARTS\MS_CONNECTOR_Library.schlib; Mfr_name: SULLINS CONNECTOR; Mfr_part_number: PREC010DAAN-RC; Mistral Part No: 150021070022-R; Package: THRU-HOLE; Part_type: CONNECTOR\HEADERS; Project: TI_AM335x SK_BRD; RoHS: RoHS; Temperature: -40°C+105°C; Tolerance: NA; Voltage: NA; Wattage: NA; Weight: NA; Datasheet: Y:\MIS_DATABASE\DATASHEETS\CONNECTORS\PRPCXXDXXN-SER.PDF
R55 R331 R654 = RESISTOR: RES 0E 1/20W 5% 0201; Chkd/date: NAVEED/301214; Crtd /date: MUDDU/120710; Custom_Duty: 15%; Customs_HS_Code: 85332119; Distributor_name: DIGIKEY; Distributor_part_number: 311-0.0NCT-ND; Footprint Path: Y:\MIS_DATABASE\Library\ALTIUM_TOOL\PCB_FOOTPRINTS\Altium_Footprint_Lib.PcbLib; Height: 0.26MM; Library Path: Y:\MIS_DATABASE\Library\ALTIUM_TOOL\SCHEMATICS_PARTS\MS_DISCRETE_Library.schlib; Mfr_name: YAGEO AMERICA; Mfr_part_number: RC0201JR-070RL; Mistral Part No: 110010070067-R; Package: 0201; Part_type: RESISTORS\FIXED; Project: PB_BUGBASE; RoHS: RoHS; SIGNAL_MODEL: RESISTOR_RES0201_0-5_0E_0E; Temperature: -55°C+125°C; Tolerance: 5%; Voltage: NA; Wattage: 1/20W; Weight: 0.17mg; Datasheet: Y:\MIS_DATABASE\DATASHEETS\RESISTORS\RCXXXXL-SER_MAR18.PDF
R56 = RESISTOR: RES 22E 1/20W 5% 0201; Chkd/date: PRADEEP/220424; Crtd /date: SHANKARI/220424; Custom_Duty: 15%; Customs_HS_Code: 85332119; Distributor_name: DIGIKEY; Distributor_part_number: 311-22NCT-ND; Footprint Path: Y:\MIS_DATABASE\Library\ALTIUM_TOOL\PCB_FOOTPRINTS\Altium_Footprint_Lib.PcbLib; Height: 0.26MM; Library Path: Y:\MIS_DATABASE\Library\ALTIUM_TOOL\SCHEMATICS_PARTS\MS_DISCRETE_Library.schlib; Manufacturer: YAGEO; Mfr_name: YAGEO AMERICA; Mfr_part_number: RC0201JR-0722RL; Mistral Part No: 110024040012-R; Package: 0201; Part_type: RESISTORS\FIXED; Project: J7AEN_SKEVM; RoHS: RoHS; Temperature: -55°C+125°C; Tolerance: 5%; Voltage: NA; Wattage: 1/20W; Weight: NA; Datasheet: Y:\MIS_DATABASE\DATASHEETS\RESISTORS\RC0201JR-0722RL.PDF
R74 = RESISTOR: RES 33E 1/20W 5% 0201; Chkd/date: VASANTHA/061216; Crtd /date: MAZHAR/170505; Custom_Duty: 15%; Customs_HS_Code: 85332119; Distributor_name: DIGIKEY; Distributor_part_number: P33AGCT-ND; Footprint Path: Y:\MIS_DATABASE\Library\ALTIUM_TOOL\PCB_FOOTPRINTS\Altium_Footprint_Lib.PcbLib; Height: 0.26MM; Library Path: Y:\MIS_DATABASE\Library\ALTIUM_TOOL\SCHEMATICS_PARTS\MS_DISCRETE_Library.schlib; Mfr_name: PANASONIC-ECG; Mfr_part_number: ERJ-1GEJ330C; Mistral Part No: 110010070052-R; Package: 0201; Part_type: RESISTORS\FIXED; Project: G4SLIM; RoHS: RoHS; Temperature: -55°C+125°C; Tolerance: 5%; Voltage: NA; Wattage: 1/20W; Weight: 0.15mg; Datasheet: Y:\MIS_DATABASE\DATASHEETS\RESISTORS\PAN-ERJXGE-FEB06.PDF
R421 = RESISTOR: RES 0E 1/16W JUMPER 0402; Chkd/date: VASANTHA/201216; Crtd /date: MUDDU/190810; Custom_Duty: 15%; Customs_HS_Code: 85332119; Distributor_name: DIGIKEY; Distributor_part_number: 541-0.0JCT-ND; Footprint Path: Y:\MIS_DATABASE\Library\ALTIUM_TOOL\PCB_FOOTPRINTS\Altium_Footprint_Lib.PcbLib; Height: 0.40MM; Library Path: Y:\MIS_DATABASE\Library\ALTIUM_TOOL\SCHEMATICS_PARTS\MS_DISCRETE_Library.schlib; Mfr_name: VISHAY; Mfr_part_number: CRCW04020000Z0ED; Mistral Part No: 110010080019-R; Package: 0402; Part_type: RESISTORS\FIXED; Project: PB_BUGBASE; RoHS: RoHS; Temperature: -55°C+155°C; Tolerance: NA; Voltage: NA; Wattage: 1/16W; Weight: 0.65mg; Datasheet: Y:\MIS_DATABASE\DATASHEETS\RESISTORS\CRCW0603.PDF
R422 R441 = RESISTOR: RES 0E 1/20W 5% 0201; Chkd/date: NAVEED/301214; Crtd /date: MUDDU/120710; Custom_Duty: 15%; Customs_HS_Code: 85332119; Distributor_name: DIGIKEY; Distributor_part_number: 311-0.0NCT-ND; Footprint Path: Y:\MIS_DATABASE\Library\ALTIUM_TOOL\PCB_FOOTPRINTS\Altium_Footprint_Lib.PcbLib; Height: 0.26MM; Library Path: Y:\MIS_DATABASE\Library\ALTIUM_TOOL\SCHEMATICS_PARTS\MS_DISCRETE_Library.schlib; Mfr_name: YAGEO AMERICA; Mfr_part_number: RC0201JR-070RL; Mistral Part No: 110010070067-R; Package: 0201; Part_type: RESISTORS\FIXED; Project: PB_BUGBASE; RoHS: RoHS; Temperature: -55°C+125°C; Tolerance: 5%; Voltage: NA; Wattage: 1/20W; Weight: 0.17mg; Datasheet: Y:\MIS_DATABASE\DATASHEETS\RESISTORS\RCXXXXL-SER_MAR18.PDF
R442 = RESISTOR: RES 2.2K 1/20W 5% 0201; Chkd/date: VASANTHA/010117; Crtd /date: MAZHAR/010605; Custom_Duty: 15%; Customs_HS_Code: 85332119; Distributor_name: DIGIKEY; Distributor_part_number: P2.2KAGCT-ND; Footprint Path: Y:\MIS_DATABASE\Library\ALTIUM_TOOL\PCB_FOOTPRINTS\Altium_Footprint_Lib.PcbLib; Height: 0.26MM; Library Path: Y:\MIS_DATABASE\Library\ALTIUM_TOOL\SCHEMATICS_PARTS\MS_DISCRETE_Library.schlib; Mfr_name: PANASONIC-ECG; Mfr_part_number: ERJ-1GEJ222C; Mistral Part No: 110009030427-R; Package: 0201; Part_type: RESISTORS\FIXED; Project: G4SLIM; RoHS: RoHS; Temperature: -55°C+125°C; Tolerance: 5%; Voltage: NA; Wattage: 1/20W; Weight: 0.15mg; Datasheet: Y:\MIS_DATABASE\DATASHEETS\RESISTORS\PAN-ERJXGE-FEB06.PDF
R445 = RESISTOR: RES 100K 1/10W 1% 0402; Chkd/date: VASANTHA/201216; Crtd /date: MAZHAR/130306; Custom_Duty: 15%; Customs_HS_Code: 85332119; Distributor_name: DIGIKEY; Distributor_part_number: P100KLCT-ND; Footprint Path: Y:\MIS_DATABASE\Library\ALTIUM_TOOL\PCB_FOOTPRINTS\Altium_Footprint_Lib.PcbLib; Height: 0.40MM; Library Path: Y:\MIS_DATABASE\Library\ALTIUM_TOOL\SCHEMATICS_PARTS\MS_DISCRETE_Library.schlib; Mfr_name: PANASONIC-ECG; Mfr_part_number: ERJ-2RKF1003X; Mistral Part No: 110009030187-R; Package: 0402; Part_type: RESISTORS\FIXED; Project: J32; RoHS: RoHS; Temperature: -55°C+155°C; Tolerance: 1%; Voltage: NA; Wattage: 1/10W; Weight: 0.8mg; Datasheet: Y:\MIS_DATABASE\DATASHEETS\RESISTORS\PAN-ERJSER_NOV17.PDF
R501 R504 R506 R508 R511 R513 R516 R518 = RESISTOR: RES 1.1K 1/20W 1% 0201; Chkd/date: MAZHAR/121207; Crtd /date: USMAN/121207; Custom_Duty: 15%; Customs_HS_Code: 85332119; Distributor_name: DIGIKEY; Distributor_part_number: P1.10KABCT-ND; Footprint Path: Y:\MIS_DATABASE\Library\ALTIUM_TOOL\PCB_FOOTPRINTS\Altium_Footprint_Lib.PcbLib; Height: 0.26MM; Library Path: Y:\MIS_DATABASE\Library\ALTIUM_TOOL\SCHEMATICS_PARTS\MS_DISCRETE_Library.schlib; Mfr_name: PANASONIC-ECG; Mfr_part_number: ERJ-1GEF1101C; Mistral Part No: 110009030097-R; Package: 0201; Part_type: RESISTORS\FIXED; Project: SD_WATERLOO; RoHS: RoHS; Temperature: -55°C+125°C; Tolerance: 1%; Voltage: NA; Wattage: 1/20W; Weight: 0.15mg; Datasheet: Y:\MIS_DATABASE\DATASHEETS\RESISTORS\PAN-ERJSER_NOV17.PDF
RA1 RA2 = RESARR_ISO4: RES ARRAY 1K 31mW 5% 0201-4; Chkd/date: NAVEED/110515; Crtd /date: VASANTHA/080515; Custom_Duty: 15%; Customs_HS_Code: 85332119; Distributor_name: DIGIKEY; Distributor_part_number: Y6102CT-ND; Footprint Path: Y:\MIS_DATABASE\Library\ALTIUM_TOOL\PCB_FOOTPRINTS\Altium_Footprint_Lib.PcbLib; Height: 0.45MM; Library Path: Y:\MIS_DATABASE\Library\ALTIUM_TOOL\SCHEMATICS_PARTS\MS_DISCRETE_Library.schlib; Manufacturer: PANASONIC-ECG; Mfr_part_number: EXB-18V102JX; Mistral Part No: 110015050003-R; Package: 0201-4; Part_type: RESISTORS\ARRAY; Project: FREE SCALE NANO; RoHS: RoHS; Temperature: -55°C+125°C; Tolerance: 5%; Voltage: NA; Wattage: 31mW; Weight: 1mg; Datasheet: Y:\MIS_DATABASE\DATASHEETS\RESISTORS\EXB-18V.PDF
U62 = TPS22912CYZVR_DSBGA4: IC 3.6V 500mA 78mE ON-RESISTANCE LOAD SWITCH WITH CONTROLLED TURNON DSBGA4; Chkd/date: MANIRAJA/170920; Crtd /date: ALVY/160920; Custom_Duty: 15%; Customs_HS_Code: 85423100; Distributor_name: DIGIKEY; Distributor_part_number: 296-24472-1-ND; Footprint Path: Y:\MIS_DATABASE\Library\ALTIUM_TOOL\PCB_FOOTPRINTS\Altium_Footprint_Lib.PcbLib; Height: 0.50MM; Library Path: Y:\MIS_DATABASE\Library\ALTIUM_TOOL\SCHEMATICS_PARTS\MS_MISCPOWER_Library.schlib; Mfr_name: TEXAS INSTRUMENTS; Mistral Part No: 142020090007-R; Package: DSBGA4; Part_type: ICS\POWER; Project: AM64X_SKEVM; RoHS: RoHS; Temperature: -40°C+85°C; Tolerance: NA; Voltage: NA; Wattage: NA; Weight: 0.7mg; Datasheet: Y:\MIS_DATABASE\DATASHEETS\ICS\POWER\TPS22901-2-3.PDF
Y1 = CRY: CRY 32.768KHz 9pF SMD; Chkd/date: VASANTHA/090419; Crtd /date: ALVY/090419; Custom_Duty: 24%; Customs_HS_Code: 85439000; Distributor_name: DIGIKEY; Distributor_part_number: XC2160CT-ND; Footprint Path: Y:\MIS_DATABASE\Library\ALTIUM_TOOL\PCB_FOOTPRINTS\Altium_Footprint_Lib.PcbLib; Height: 0.90MM; Library Path: Y:\MIS_DATABASE\Library\ALTIUM_TOOL\SCHEMATICS_PARTS\MS_DISCRETE_Library.schlib; Mfr_name: ECS INC; Mfr_part_number: ECS-.327-9-34QCS-TR; Mistral Part No: 130019040003-R; Package: SMD; Part_type: CRYSTAL; Project: J7ES_SOM_DUAL-LEO_PMIC; RoHS: RoHS; Temperature: -40°C+125°C; Tolerance: NA; Voltage: NA; Wattage: NA; Weight: 16mg; Datasheet: Y:\MIS_DATABASE\DATASHEETS\MISC\CRY_OSC\ECS-34Q.PDF
U12 = AM62-EVM_BGA425: IC AM62 SoC MICROPROCESSOR BGA425; Chkd/date: ALVY/110621; Crtd /date: MANIRAJA/110621; Custom_Duty: 15%; Customs_HS_Code: 85423100; Distributor_name: NA; Distributor_part_number: NA; Footprint Path: Y:\MIS_DATABASE\Library\ALTIUM_TOOL\PCB_FOOTPRINTS\Altium_Footprint_Lib.PcbLib; Height: 0.65MM; Library Path: Y:\MIS_DATABASE\Library\ALTIUM_TOOL\SCHEMATICS_PARTS\MS_MICROPROCESSOR_Library.schlib; Mfr_name: TEXAS INSTRUMENTS; Mistral Part No: 141221060001; Package: BGA425; Part_type: ICS\DIGITAL\MICROPROCESSOR; Project: AM62_EVM_BRD; RoHS: NA; Temperature: NA; Tolerance: NA; Voltage: NA; Wattage: NA; Weight: NA; Datasheet: Y:\MIS_DATABASE\DATASHEETS\ICS\DIGITAL\MICROCONTROLLER\AM62-SoC_SVB.PDF

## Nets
DGND: C75.2 C79.2 C174.2 C175.2 C177.1 C182.1 C183.1 C184.1 C187.1 C188.1 C379.2 C381.1 C387.2 C391.2 C452.1 C453.1 C460.1 C461.1 C465.2 C471.1 C475.1 C476.1 C478.1 C479.1 C480.1 C481.1 C482.2 C483.1 C485.1 C488.1 C489.1 C490.1 D7.1 J10.2 J15.5(GND) R445.1 R558.1 R577.1 R593.1 R601.1 R609.1 R612.1 U44.4(GND) U46.1(GND1) U46.5(GND2) U46.10(AGND) U46.11(GND3) U46.13(TEST) U46.15(GND4) U46.25(GND5) U46.35(GND6) U46.47(GND7) U46.51(GND8) U62.B1(GND) U84.8(GND1) U84.9(GND2) U84.14(~{2OE}) U84.15(~{1OE}) U87.5(VSS) U92.8(GND1) U92.9(GND2) U92.14(~{2OE}) U92.15(~{1OE}) U93.5(1A2) U93.7(2A2) U93.8(GND1) U93.9(GND2) U93.10(2B2) U93.12(1B2) U93.14(~{2OE}) U93.15(~{1OE}) U95.3(GND) U95.7(EP) U97.8(GND1) U97.9(GND2) U97.14(~{2OE}) U97.15(~{1OE}) Y3.2 Y3.4 ; also on sheet 1 10 11 12 13 14 15 16 17 18 19 20 21 22 23 24 25 26 27 28 29 30 33 34 35 36 37 38 39 40 41 42 43
VCC3V3_PRU: C379.1 C381.2 C387.1 J10.1 R442.1 U62.A1(VOUT)
VCC_1V8_FT4232: C182.2 C183.2 C461.2 C465.1 U46.12(VCORE) U46.37(VCORE) U46.49(VREGOUT) U46.64(VCORE)
VCC_3V3_FT4232: C177.2 C187.2 C188.2 C453.2 C460.2 C476.2 C478.2 C482.1 C485.2 C488.2 FL25.2 FL26.2 LD13.2(ANODE) R541.2 R542.2 R543.2 U46.20(VCCIO) U46.31(VCCIO) U46.42(VCCIO) U46.50(VREGIN) U46.56(VCCIO) U84.16(VCCB) U87.8(VCC) U92.16(VCCB) U93.16(VCCB) U95.1(OUT) U97.16(VCCB)
VCC_3V3_SYS: C391.1 C452.2 C475.2 C481.2 C489.2 R71.1 R73.1 R555.2 R561.1 R573.1 R578.2 R599.1 R602.2 R606.2 R611.1 U62.A2(VIN) U84.1(VCCA) U92.1(VCCA) U93.1(VCCA) U97.1(VCCA) ; also on sheet 10 12 13 14 18 19 20 22 23 24 25 26 27 29 30 33 34 35 36 37 38 39 40 41 42 43
BOOTMODE0: R518.1 ; also on sheet 27
BOOTMODE1: R516.1 ; also on sheet 27
BOOTMODE2: R513.1 ; also on sheet 27
BOOTMODE3: R511.1 ; also on sheet 27
BOOTMODE4: R508.1 ; also on sheet 27
BOOTMODE5: R506.1 ; also on sheet 27
BOOTMODE6: R504.1 ; also on sheet 27
BOOTMODE7: R501.1 ; also on sheet 27
BOOTMODE8: RA2.3 ; also on sheet 27
BOOTMODE9: RA2.4 ; also on sheet 27
BOOTMODE10: RA2.2 ; also on sheet 27
BOOTMODE11: RA1.1 ; also on sheet 27
BOOTMODE12: RA1.2 ; also on sheet 27
BOOTMODE13: RA2.1 ; also on sheet 27
BOOTMODE14: RA1.4 ; also on sheet 27
BOOTMODE15: RA1.3 ; also on sheet 27
CPSW_RGMII_INTn/PRU_INTn: R441.1 ; also on sheet 23 42
EXP_GPIO0_33: U12.L24(GPMC0_OEN_REN) ; also on sheet 33
EXP_GPIO0_36: U12.N20(GPMC0_BE1N) ; also on sheet 33
EXP_GPIO0_38: U12.V25(GPMC0_WAIT1) ; also on sheet 33
EXP_GPIO0_39: U12.K25(GPMC0_WPN) ; also on sheet 33
EXP_GPIO0_40/PR0_ECAP0_IN_APWM_OUT: U12.M22(GPMC0_DIR) ; also on sheet 33
EXP_GPIO0_41: U12.M21(GPMC0_CSN0) ; also on sheet 33
EXP_GPIO0_42: U12.L21(GPMC0_CSN1) ; also on sheet 33
FT4232_DO: R541.1 R551.2 U87.4(DO)
FT4232_EECLK: R542.1 U46.62(EECLK) U87.2(CLK)
FT4232_EECS: R543.1 U46.63(EECS) U87.1(CS)
FT4232_EEDATA: R551.1 U46.61(EEDATA) U87.3(DI)
FT4232_MCU_UART0_CTS_3V3: U46.53(DDBUS2) U84.10(2B2)
FT4232_MCU_UART0_RTS_3V3: U46.54(DDBUS3) U84.12(1B2)
FT4232_MCU_UART0_RX_3V3: U46.48(DDBUS0) U84.11(2B1)
FT4232_MCU_UART0_TX_3V3: U46.52(DDBUS1) U84.13(1B1)
FT4232_REF: R593.2 U46.6(REF)
FT4232_RESET: C184.2 R266.1 U46.14(~{RESET})
FT4232_SOC_UART0_RX_3V3: U46.16(ADBUS0) U93.11(2B1)
FT4232_SOC_UART0_TX_3V3: U46.17(ADBUS1) U93.13(1B1)
FT4232_SOC_UART1_CTS_3V3: U46.28(BDBUS2) U97.10(2B2)
FT4232_SOC_UART1_RTS_3V3: U46.29(BDBUS3) U97.12(1B2)
FT4232_SOC_UART1_RX_3V3: U46.26(BDBUS0) U97.11(2B1)
FT4232_SOC_UART1_TX_3V3: U46.27(BDBUS1) U97.13(1B1)
FT4232_USB_DM: J15.2(D-) U44.5(IO2) U46.7(DM)
FT4232_USB_DP: J15.3(D+) U44.3(IO1) U46.8(DP)
FT4232_USB_VBUS: C480.2 C483.2 D7.2 J15.1(VBUS) U44.1(VCC) U95.4(EN) U95.6(IN)
FT4232_WKUP_UART0_CTS_3V3: U46.40(CDBUS2) U92.10(2B2)
FT4232_WKUP_UART0_RTS_3V3: U46.41(CDBUS3) U92.12(1B2)
FT4232_WKUP_UART0_RX_3V3: U46.38(CDBUS0) U92.11(2B1)
FT4232_WKUP_UART0_TX_3V3: U46.39(CDBUS1) U92.13(1B1)
FT_PWREN#: R257.1 U46.60(~{PWREN})
HFOSC0_CLKOUT_32K: U12.A12(WKUP_CLKOUT0) ; also on sheet 18
MCASP1_ACLKX: R56.1 ; also on sheet 39
MCASP1_AFSX: R331.1 ; also on sheet 39
MCASP1_AXR0: R55.1 ; also on sheet 39
MCASP1_AXR2: R654.1 ; also on sheet 39
MCU_RESETSTATz: R421.1 ; also on sheet 34 42
MCU_UART0_CTS_3V3: U84.7(2A2) ; also on sheet 34
MCU_UART0_RTS_3V3: U84.5(1A2) ; also on sheet 34
MCU_UART0_RX_3V3: U84.6(2A1) ; also on sheet 34
MCU_UART0_TX_3V3: R561.2 U84.4(1A1) ; also on sheet 34
PR0_PRU0_GPO0: J10.13 R518.2 U12.M25(GPMC0_AD0)
PR0_PRU0_GPO1: J10.14 R516.2 U12.N23(GPMC0_AD1)
PR0_PRU0_GPO2: J10.15 R513.2 U12.N24(GPMC0_AD2)
PR0_PRU0_GPO3: J10.16 R511.2 U12.N25(GPMC0_AD3)
PR0_PRU0_GPO4: J10.17 R508.2 U12.P24(GPMC0_AD4)
PR0_PRU0_GPO5: J10.18 R506.2 U12.P22(GPMC0_AD5)
PR0_PRU0_GPO6: J10.19 R504.2 U12.P21(GPMC0_AD6)
PR0_PRU0_GPO7: J10.20 R501.2 U12.R23(GPMC0_AD7)
PRU_3V3_EN: R445.2 U62.B2(ON) ; also on sheet 39
PRU_DETECT: J10.3 ; also on sheet 39
PRU_INTn: J10.5 R441.2 R442.2
PRU_RESETz: J10.4 R421.2 R422.2
RESETSTATz: R422.1 ; also on sheet 13 19 20 21 23 24 27 33 37 39 40 41 42
SoC_I2C0_SCL: J10.6 ; also on sheet 10 13 22 33 37 42
SoC_I2C0_SDA: J10.8 ; also on sheet 10 13 22 33 37 42
SoC_I2C2_SCL: U12.K22(GPMC0_CSN2) ; also on sheet 33
SoC_I2C2_SDA: U12.K24(GPMC0_CSN3) ; also on sheet 33
SOC_RGMII_MDC: U12.AD24(MDIO0_MDC) ; also on sheet 23 24
SOC_RGMII_MDIO: U12.AB22(MDIO0_MDIO) ; also on sheet 23 24
SOC_UART0_RX_3V3: U93.6(2A1) ; also on sheet 42
SOC_UART0_TX_3V3: R599.2 U93.4(1A1) ; also on sheet 42
SOC_UART1_CTS: TP61.1(TP) U97.7(2A2) ; also on sheet 37
SOC_UART1_RTS: TP60.1(TP) U97.5(1A2) ; also on sheet 37
SOC_UART1_RXD: TP57.1(TP) U97.6(2A1) ; also on sheet 37
SOC_UART1_TXD: R611.2 TP58.1(TP) U97.4(1A1) ; also on sheet 37
SoC_VOUT0_DATA16: RA2.6 U12.R24(GPMC0_AD8) ; also on sheet 41
SoC_VOUT0_DATA17: RA2.5 U12.R25(GPMC0_AD9) ; also on sheet 41
SoC_VOUT0_DATA18: RA2.7 U12.T25(GPMC0_AD10) ; also on sheet 41
SoC_VOUT0_DATA19: RA1.8 U12.R21(GPMC0_AD11) ; also on sheet 41
SoC_VOUT0_DATA20: RA1.7 U12.T22(GPMC0_AD12) ; also on sheet 41
SoC_VOUT0_DATA21: RA2.8 U12.T24(GPMC0_AD13) ; also on sheet 41
SoC_VOUT0_DATA22: RA1.5 U12.U25(GPMC0_AD14) ; also on sheet 41
SoC_VOUT0_DATA23: RA1.6 U12.U24(GPMC0_AD15) ; also on sheet 41
UART_SHIELD: J15.6(SH1) J15.7(SH2) J15.8(SH3) J15.9(SH4) R612.2
VPHY_3V3_FT4232: C471.2 FL25.1 U46.4(VPHY)
VPLL_3V3_FT4232: C479.2 FL26.1 R266.2 U46.9(VPLL)
VSEL_SD_SOC: U12.P25(GPMC0_CLK) ; also on sheet 13
WKUP_I2C0_SCL: R73.2 R74.2 ; also on sheet 25
WKUP_I2C0_SDA: R71.2 U12.A9(WKUP_I2C0_SDA) ; also on sheet 25
WKUP_LFOSCO_XI: C75.1 U12.C2(WKUP_LFOSC0_XI) Y1.1
WKUP_LFOSCO_XO: C79.1 U12.C1(WKUP_LFOSC0_XO) Y1.2
WKUP_UART0_CTS_3V3: U12.C6(WKUP_UART0_CTSN) U92.7(2A2)
WKUP_UART0_RTS_3V3: U12.A4(WKUP_UART0_RTSN) U92.5(1A2)
WKUP_UART0_RX_3V3: U12.B4(WKUP_UART0_RXD) U92.6(2A1)
WKUP_UART0_TX_3V3: R573.2 U12.C5(WKUP_UART0_TXD) U92.4(1A1)
N16856152: C175.1 U46.3(OSCO) Y3.3
N16856224: C174.1 U46.2(OSCI) Y3.1
N16857368: C490.2 U95.2(NR/FB)
N16894003: R577.2 U92.3(2DIR)
N16894009: R578.1 U92.2(1DIR)
N17378539: LD13.1(CATHODE) R257.2
N17395932: R74.1 U12.B9(WKUP_I2C0_SCL)
N18571509: R609.2 U97.3(2DIR)
N18571515: R606.1 U97.2(1DIR)
N19066697: R56.2 U12.M24(GPMC0_BE0N_CLE)
N19066711: R331.2 U12.U23(GPMC0_WAIT0)
N19066744: R55.2 U12.L25(GPMC0_WEN)
N20055845: R654.2 U12.L23(GPMC0_ADVN_ALE)
N20674580: R602.1 U93.2(1DIR)
N20674790: R601.2 U93.3(2DIR)
N20689650: R558.2 U84.3(2DIR)
N20689656: R555.1 U84.2(1DIR)

Not connected (* = marked no-connect by the designer): J10 7* 9* 10* 11* 12*; J15 4(ID)*; U12 B7(PMIC_LPM_EN0)*; U44 2(NC)*; U46 18(ADBUS2)* 19(ADBUS3)* 21(ADBUS4)* 22(ADBUS5)* 23(ADBUS6)* 24(ADBUS7)* 30(BDBUS4)* 32(BDBUS5)* 33(BDBUS6)* 34(BDBUS7)* 36(~{SUSPEND})* 43(CDBUS4)* 44(CDBUS5)* 45(CDBUS6)* 46(CDBUS7)* 55(DDBUS4)* 57(DDBUS5)* 58(DDBUS6)* 59(DDBUS7)*; U87 6(NC1)* 7(NC2)*; U95 5(NC)*

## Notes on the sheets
sheet 31
- FT4232 UART
- Silk: UART
- 90E
- DIR=H : A ->B
  DIR=L : B ->A
- D-Note :-
  Follow SK-AM62P-LP for latest
  FT4232 implementations
- D-Note :- Add a
  filter cap (0.1uF)
- DIR=H : A ->B
  DIR=L : B ->A
- FT4232: 5V to 3.3V@500mA LDO
- ECS-120-18-30B-AGN-TR
- DIR=H : A ->B
  DIR=L : B ->A
- EEPROM
- R-Note:-
  Verify the implementation with
  the device manufacturer
- DIR=H : A ->B
  DIR=L : B ->A
sheet 32
- D-Note :-
  Open-drain output type buffer I2C interfaces
  have slew rate requirement when pulled to 3.3 V.
  An RC is recommended for slew rate control
  Refer SK-AM62P-LP schematics
- D-Note :-
  A pullup is recommended for Open
  drain output type I2C interfaces
  irrespective of the IO configuration
  Refer pin connectivity table of SOC
  data sheet
- SOC WKUP DOMAIN
- D-Note :-
  The only LFOSC0 register bits that should be changed by the customer
  are BP_C, PD_C, and CTRLMMR_WKUP_LFXOSC_TRIM[18:16], where PD_C is
  reset (0) to enable the oscillator and the BP_C bit is only set (1) to
  place the oscillator in bypass mode when using an LVCMOS clock
  source.The CTRLMMR_WKUP_LFXOSC_TRIM[18:16] bits are set based on the
  actual capacitance load applied to the crystal, as defined by the Load
  Capacitance Equation. The load capacitance range of the crystal will be
  half of the recommended capacitor value range since there are connected
  in series with the crystals resonate circuit.
- SOC GPMC INTERFACE
- D-Note :-
  WKUP_CLKOUT0 is a buffered output of
  the high frequency oscillator (HFOSC0)
  available during power-up as default
- ECS-.327-9-34QCS-TR
- D-Note :-
  WKUP LFOSC0 has limited use
  case. Provide provision to
  ground Xi when not used. Refer
  SOC data sheet
- D-Note
  Add a series resistor 0R when used as GPMC0_CLK
- D-Note :-
  Refer SoC data sheet for the recommended circuit configuration
  during preproduction PCB and the production PCB
- D-Note :-
  Shorting of bootmode inputs (IOs) is not recommended or allowed since the IOs
  have alternate functions that could be configured after boot
  Shorting the bootmode pins directly to VCC or ground directly is not recommended
  Connect each of the bootmode pins through separate resistor
  Choose the bootmode resistor value based on the use case (10K or similar)
- D-Note :-
  Delete or reduce the series resistor value  to 0R when buffers are not used,
  This resistor could be used to isolate the alternate function during testing
  Ok to use 1K standard resistor
- D-Note :-
  SOC IO buffers for signals used for GPMC interface
  are disabled during reset
  The required pulls for the interfaced signals are
  provided on the GPMC interface card
- BOOTMODE PINS
- D-Note :-
  When bootmode Isolation buffers are not used,
  connect the bootmode configuration resistors
  directly to the SOC bootmode input pins.
  Connect the SOC bootmode signal used for alternate
  function to the attached device through 0R for
  isolation or testing.
- R-Note :- Resistors are used to
  isolate the BOOTMODE control logic
  after the value is latched
- PRU HEADER
- POWER SWITCH FOR PRU HEADER
- D-Note :-
  Any SoC IO that has a trace connected but not being driven
  actively needs to be connected to an external pull.
  When adding pull is not feasible, ensure the traces are routed
  away from noisy signals
- D-Note :-
  Can support custom design
  to source 500mA
- Silk: PRU HDR
- 3V3 supply of PRU Header is limited to sourcing 500mA max.
- D-Note:- Processor IOs connected to PRU Header are not fail-safe.
  No external input shall be driven when Starter Kit is not powered-up.
